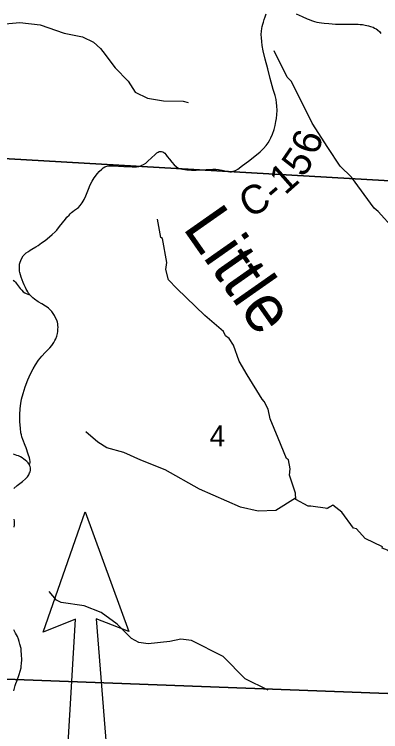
# Model space of a CAD drawing. Extents: x 396.2 to 468.4, y 232.6 to 279.1.
# Drawn here: x 420.393 to 421.121, y 267.097 to 268.52 of the extents above; entities that cross this region are included whole.
import ezdxf

# ---------------------------------------------------------------- set-up
doc = ezdxf.new("R2010")
doc.units = 0
for name, color, linetype in [('GM_X_County_Road', 7, 'Continuous'), ('GM_X_County_Road_Text', 7, 'Continuous'), ('GM_X_Minor_River', 7, 'Continuous'), ('GM_X_Minor_River_Text', 7, 'Continuous'), ('GM_X_Section', 7, 'Continuous'), ('GM_X_Section_Text', 7, 'Continuous'), ('TX_P_1', 7, 'Continuous')]:
    doc.layers.add(name, color=color, linetype=linetype)

msp = doc.modelspace()

# ---------------------------------------------------------------- linework, layer by layer
at = {"layer": 'GM_X_County_Road'}
for points in [[(420.4165, 267.9748), (420.415, 267.9778), (420.4126, 267.9832), (420.4105, 267.9881), (420.4084, 267.9933), (420.4066, 267.9983), (420.4049, 268.0032), (420.4037, 268.0077), (420.4031, 268.0107), (420.4028, 268.015), (420.4028, 268.0184), (420.403, 268.0213), (420.4034, 268.0246), (420.4045, 268.0283), (420.4057, 268.0314), (420.408, 268.0364), (420.4106, 268.0406), (420.413, 268.0435), (420.4164, 268.0466), (420.4207, 268.0497), (420.4241, 268.0521), (420.4279, 268.0543), (420.4357, 268.0588), (420.4402, 268.0615), (420.4469, 268.0664), (420.4538, 268.0713), (420.4627, 268.0786), (420.468, 268.0833), (420.4737, 268.0886), (420.477, 268.0917), (420.4825, 268.0994), (420.4942, 268.1137), (420.4974, 268.1178), (420.5015, 268.1218), (420.5041, 268.1245), (420.5062, 268.1267), (420.5092, 268.1289), (420.5122, 268.1312), (420.5163, 268.1339), (420.5201, 268.1366), (420.5239, 268.1406), (420.5279, 268.146), (420.5315, 268.1524), (420.535, 268.1603), (420.54, 268.1731), (420.5438, 268.1819), (420.5476, 268.1892), (420.5515, 268.1955), (420.5578, 268.2044), (420.5611, 268.2081), (420.5666, 268.2132), (420.5696, 268.2155), (420.5729, 268.2173), (420.5765, 268.2186), (420.5808, 268.2194), (420.5845, 268.2196), (420.5888, 268.2195), (420.6107, 268.2181), (420.6273, 268.2176), (420.6318, 268.2176), (420.6359, 268.2177), (420.6402, 268.2183), (420.6427, 268.219), (420.646, 268.2205), (420.6498, 268.2223), (420.6541, 268.2251), (420.6583, 268.2287), (420.6656, 268.2353), (420.6729, 268.2421), (420.6759, 268.2451), (420.6784, 268.2469), (420.6806, 268.2478), (420.6832, 268.2481), (420.6856, 268.248), (420.6879, 268.2475), (420.6901, 268.2462), (420.6922, 268.2444), (420.6938, 268.2423), (420.6968, 268.2378), (420.701, 268.2324), (420.7056, 268.2266), (420.7106, 268.2212), (420.7143, 268.218), (420.7179, 268.2156), (420.7208, 268.2143), (420.7235, 268.2136), (420.7269, 268.2129), (420.7354, 268.2116), (420.7447, 268.2108), (420.754, 268.2107), (420.7644, 268.2115), (420.7743, 268.2125), (420.7872, 268.213), (420.7934, 268.2127), (420.7984, 268.2122), (420.8056, 268.2109), (420.811, 268.2096), (420.8174, 268.208), (420.821, 268.2076), (420.8245, 268.2078), (420.828, 268.2086), (420.832, 268.2102), (420.8367, 268.2128), (420.8465, 268.2202), (420.858, 268.229), (420.8742, 268.2416), (420.8813, 268.2476), (420.888, 268.254), (420.8933, 268.26), (420.897, 268.265), (420.8998, 268.2697), (420.9026, 268.2749), (420.9059, 268.2825), (420.9089, 268.2916), (420.9111, 268.2996), (420.9128, 268.3073), (420.9138, 268.3137), (420.9146, 268.3216), (420.9151, 268.3293), (420.9146, 268.3384), (420.9141, 268.3443), (420.9129, 268.3514), (420.9109, 268.3589), (420.9073, 268.371), (420.9013, 268.3926), (420.8963, 268.4119), (420.8913, 268.431), (420.8875, 268.4477), (420.8856, 268.4581), (420.8845, 268.466), (420.8838, 268.4735), (420.8835, 268.4803), (420.8837, 268.4866), (420.8846, 268.4919), (420.8855, 268.4961), (420.8865, 268.5006), (420.8878, 268.5048), (420.8893, 268.5097), (420.8912, 268.5149), (420.8934, 268.5213)], [(420.9528, 268.5209), (420.965, 268.5155), (420.9745, 268.5112), (420.9784, 268.5096), (420.9836, 268.5076), (420.989, 268.5059), (420.9942, 268.5048), (420.9983, 268.504), (421.0033, 268.5033), (421.0087, 268.5025), (421.0177, 268.5017), (421.0243, 268.5012), (421.0313, 268.5009), (421.0461, 268.5005), (421.0604, 268.5004), (421.076, 268.5003), (421.08, 268.5001), (421.0847, 268.4997), (421.0899, 268.4989), (421.0964, 268.4975), (421.1006, 268.4963), (421.1058, 268.4944), (421.1088, 268.4929), (421.1118, 268.4912), (421.1142, 268.4894), (421.1189, 268.4851), (421.121, 268.4824)], [(420.3907, 267.9924), (420.393, 267.9904), (420.395, 267.9885), (420.3968, 267.9865), (420.4006, 267.9815), (420.4047, 267.9761), (420.4075, 267.9728), (420.4106, 267.9698), (420.4136, 267.9676), (420.4165, 267.9659), (420.4199, 267.9646), (420.4234, 267.9638)], [(420.4233, 267.6255), (420.4238, 267.628), (420.4242, 267.6307), (420.4241, 267.633), (420.4236, 267.6365), (420.4227, 267.6403), (420.4204, 267.6473), (420.4164, 267.6596), (420.4145, 267.6646), (420.41, 267.6762), (420.408, 267.6819), (420.4068, 267.6859), (420.406, 267.6898), (420.4048, 267.6987), (420.4041, 267.7112), (420.404, 267.7258), (420.4045, 267.7375), (420.405, 267.7431), (420.4056, 267.7481), (420.4071, 267.7568), (420.4101, 267.7677), (420.4141, 267.7807), (420.4197, 267.7949), (420.4248, 267.8067), (420.4301, 267.8168), (420.435, 267.8249), (420.4411, 267.8338), (420.4477, 267.8419), (420.4541, 267.8489), (420.4635, 267.8586), (420.4674, 267.8633), (420.4711, 267.8687), (420.4733, 267.8728), (420.4751, 267.8765), (420.4771, 267.8814), (420.4785, 267.8865), (420.4791, 267.8909), (420.4796, 267.8953), (420.4797, 267.8993), (420.4796, 267.9027), (420.4791, 267.9062), (420.4783, 267.9095), (420.4771, 267.9131), (420.4749, 267.9178), (420.4725, 267.9225), (420.47, 267.9264), (420.4673, 267.9302), (420.4643, 267.9337), (420.461, 267.9368), (420.458, 267.9391), (420.4546, 267.9413), (420.4477, 267.9454), (420.4404, 267.9499), (420.4329, 267.9549), (420.4296, 267.9575), (420.4268, 267.9601), (420.4234, 267.9638), (420.4212, 267.9666), (420.4194, 267.9694), (420.4174, 267.9729), (420.4165, 267.9748)], [(420.3917, 267.5795), (420.3986, 267.5849), (420.409, 267.5928), (420.415, 267.5982), (420.4187, 267.6023), (420.4214, 267.6063), (420.4233, 267.6101), (420.4242, 267.6126), (420.4247, 267.6151), (420.425, 267.6176), (420.4247, 267.6202), (420.4242, 267.623), (420.4233, 267.6255), (420.4218, 267.6279), (420.4201, 267.63), (420.4175, 267.6328), (420.4147, 267.6354), (420.4118, 267.6376), (420.4086, 267.6398), (420.4049, 267.6419), (420.4011, 267.6438), (420.3981, 267.645), (420.3947, 267.6461), (420.391, 267.6472)], [(420.3923, 267.5028), (420.3929, 267.5074), (420.393, 267.5109), (420.3929, 267.5145), (420.3925, 267.5182)], [(420.3919, 267.1777), (420.3931, 267.183), (420.3946, 267.1883), (420.3958, 267.1926), (420.3975, 267.1972), (420.4024, 267.2104), (420.4046, 267.217), (420.4061, 267.2235), (420.4067, 267.2274), (420.4072, 267.2313), (420.4075, 267.2401), (420.4073, 267.2491), (420.4067, 267.2578), (420.4061, 267.262), (420.4041, 267.2703), (420.4027, 267.2755), (420.4009, 267.2803), (420.399, 267.2853), (420.3955, 267.2922), (420.392, 267.2986)]]:
    msp.add_lwpolyline(points, dxfattribs=at)
at = {"layer": 'GM_X_Minor_River'}
for points in [[(420.3596, 268.5002), (420.404, 268.5041), (420.4439, 268.4994), (420.4918, 268.483), (420.5282, 268.4758), (420.5502, 268.4648), (420.5638, 268.4526), (420.5689, 268.4464), (420.5929, 268.4137), (420.6193, 268.3874), (420.633, 268.3654), (420.6572, 268.354), (420.6895, 268.3484), (420.7285, 268.3479), (420.7382, 268.3453)], [(421.1471, 268.0942), (421.1157, 268.1286), (421.1076, 268.1357), (421.0629, 268.1971), (421.0405, 268.2187), (421.016, 268.2559), (420.9849, 268.304), (420.9439, 268.3866), (420.9351, 268.3952), (420.9092, 268.448)], [(421.015, 267.5394), (420.9821, 267.5444), (420.9765, 267.544), (420.9519, 267.5576), (420.9515, 267.5702), (420.9397, 267.6055), (420.9412, 267.6184), (420.9374, 267.6359), (420.9337, 267.6389), (420.9174, 267.6788), (420.9015, 267.7172), (420.8973, 267.7369), (420.889, 267.7521), (420.8855, 267.7563), (420.8556, 267.8048), (420.8394, 267.8322), (420.8284, 267.8637), (420.8197, 267.8766), (420.8125, 267.8819), (420.8083, 267.891), (420.7716, 267.9228), (420.716, 267.9759), (420.6993, 267.993), (420.694, 268.0139), (420.6959, 268.0276), (420.6876, 268.0751), (420.6841, 268.0773), (420.6773, 268.1134)], [(420.9515, 267.56), (420.9125, 267.5355), (420.8776, 267.5344), (420.8423, 267.542), (420.761, 267.5776), (420.6927, 267.6166), (420.6441, 267.6352), (420.6105, 267.6504), (420.5764, 267.6602), (420.559, 267.671), (420.535, 267.6915)], [(421.3189, 267.2914), (421.2969, 267.3061), (421.2606, 267.3372), (421.2405, 267.3519), (421.2129, 267.3857), (421.2099, 267.3861), (421.1781, 267.427), (421.152, 267.4407), (421.1342, 267.4566), (421.124, 267.4611), (421.1247, 267.4638), (421.0903, 267.4801), (421.0729, 267.4994), (421.0665, 267.5005), (421.0434, 267.5324), (421.026, 267.5464), (421.0138, 267.5395), (421.0227, 267.5445)], [(420.8975, 267.1791), (420.8517, 267.2015), (420.8077, 267.2461), (420.7451, 267.2774), (420.7236, 267.28), (420.702, 267.2757), (420.6591, 267.271), (420.6403, 267.2739), (420.6254, 267.2816), (420.5975, 267.3102), (420.5654, 267.3332), (420.5314, 267.3465), (420.4862, 267.3529), (420.4769, 267.3577), (420.4619, 267.3749)]]:
    msp.add_lwpolyline(points, dxfattribs=at)
at = {"layer": 'GM_X_Section'}
for points in [[(420.3647, 269.2542), (421.4251, 269.2153), (421.3567, 268.1769), (420.3017, 268.2379)], [(421.3567, 268.1769), (421.2935, 267.1662), (420.2353, 267.206), (420.2356, 267.2112), (420.2473, 267.3927), (420.2746, 267.8175), (420.3017, 268.2379)], [(420.2353, 267.206), (421.2935, 267.1662), (421.2281, 266.1152), (421.0364, 266.1227), (420.8385, 266.1259), (420.635, 266.1359), (420.4459, 266.1456), (420.2836, 266.1536), (420.1699, 266.1596), (420.221, 266.9787)]]:
    msp.add_lwpolyline(points, close=True, dxfattribs=at)
at = {"layer": 'TX_P_1'}
for p, q in [((420.4499, 267.294), (420.5333, 267.533)), ((420.5333, 267.533), (420.6206, 267.2958)), ((420.5145, 267.3201), (420.4499, 267.294)), ((420.4971, 267.0338), (420.5145, 267.3201)), ((420.6206, 267.2958), (420.5557, 267.3204)), ((420.5557, 267.3204), (420.5783, 267.0348))]:
    msp.add_line(p, q, dxfattribs=at)

# ---------------------------------------------------------------- texts
at = {"layer": 'GM_X_County_Road_Text'}
for s, rotation, p in [('6', 71.0324, (420.9943, 268.2385)), ('5', 55.3666, (420.9668, 268.1946)), ('1', 41.5097, (420.9307, 268.1602)), ('C', 26.6261, (420.8579, 268.1151)), ('-', 40.4737, (420.9121, 268.1443))]:
    msp.add_text(s, height=0.0568, rotation=rotation, dxfattribs=at).set_placement(p)
at = {"layer": 'GM_X_Minor_River_Text'}
msp.add_text('Little', height=0.09469, rotation=304.9993, dxfattribs=at).set_placement((420.7261, 268.0963))
at = {"layer": 'GM_X_Section_Text'}
msp.add_text('4', height=0.0419, rotation=0, dxfattribs=at).set_placement((420.7808, 267.6626))

doc.saveas('drawing.dxf')
